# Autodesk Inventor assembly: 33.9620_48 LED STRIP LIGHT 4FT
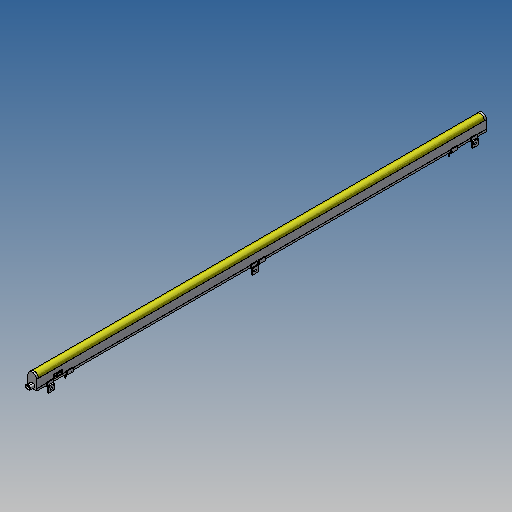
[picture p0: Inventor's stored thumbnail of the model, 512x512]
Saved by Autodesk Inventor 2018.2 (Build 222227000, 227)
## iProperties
Created: 2018-05
Part Number: 33.9620_48 LED STRIP LIGHT 4FT
Document SubType Name: Assembly
Designer: amoles
Author: amoles
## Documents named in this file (6)
- Y:\INVENTOR LIBRARIES\PARTS LIBRARY\WORKSTATION\LIGHTS OUTWATER PLASTICS\33.9620_48 LED STRIP LIGHT 4FT.iam
- Y:\INVENTOR LIBRARIES\PARTS LIBRARY\WORKSTATION\LIGHTS OUTWATER PLASTICS\SUBCOMPONENTS\33.9620 PLASTIC MOUNTING CLIP IN LINE.ipt
- Y:\INVENTOR LIBRARIES\PARTS LIBRARY\WORKSTATION\LIGHTS OUTWATER PLASTICS\SUBCOMPONENTS\33.9620 PLASTIC MOUNTING CLIP OFFSET.ipt
- Y:\INVENTOR LIBRARIES\PARTS LIBRARY\WORKSTATION\LIGHTS OUTWATER PLASTICS\SUBCOMPONENTS\33.9620_48 LED STRIP LIGHT 4FT.ipt
- Y:\INVENTOR LIBRARIES\PARTS LIBRARY\WORKSTATION\LIGHTS OUTWATER PLASTICS\SUBCOMPONENTS\33.9620 RECEPTACLE COVER.ipt
- Y:\INVENTOR LIBRARIES\PARTS LIBRARY\WORKSTATION\LIGHTS OUTWATER PLASTICS\SUBCOMPONENTS\33.9620 M3.9 MOUNTING SCREW.ipt
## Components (11 placed, 5 different names)
1. 33.9620_48 LED STRIP LIGHT 4FT:1 — Mate:1, Flush:1, Flush:4, Flush:6, Flush:10, Flush:11, Mate:2, Flush:12, Flush:13, Mate:3, Angle:1, Mate:4, Mate:5, Mate:7, Mate:8
2. 33.9620 PLASTIC MOUNTING CLIP IN LINE:1 — Mate:1, Flush:1, Flush:2, Flush:3, Flush:4, Flush:5, Flush:7, Insert:2
3. 33.9620 PLASTIC MOUNTING CLIP IN LINE:2 — Flush:2, Flush:3, Flush:8, Flush:9, Flush:12, Insert:1
4. 33.9620 PLASTIC MOUNTING CLIP OFFSET:1 — Flush:5, Flush:6, Flush:7
5. 33.9620 PLASTIC MOUNTING CLIP OFFSET:2 — Flush:8, Flush:9, Flush:10
6. 33.9620 RECEPTACLE COVER:1 — Mate:3, Angle:1, Mate:4
7. 33.9620 M3.9 MOUNTING SCREW:1 — Insert:2
8. 33.9620 M3.9 MOUNTING SCREW:2 — Insert:1
9. 33.9620 PLASTIC MOUNTING CLIP IN LINE:3 — Mate:5, Mate:7, Mate:8, Insert:3, Flush:14, Flush:15
10. 33.9620 M3.9 MOUNTING SCREW:3 — Insert:3
11. 33.9620 PLASTIC MOUNTING CLIP OFFSET:3 — Flush:14, Flush:15
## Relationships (26: Flush 15, Mate 7, Insert 3, Angle 1)
- Mate:1: 33.9620_48 LED STRIP LIGHT 4FT:1 ↔ 33.9620 PLASTIC MOUNTING CLIP IN LINE:1
- Flush:1: 33.9620_48 LED STRIP LIGHT 4FT:1 ↔ 33.9620 PLASTIC MOUNTING CLIP IN LINE:1
- Flush:2: 33.9620 PLASTIC MOUNTING CLIP IN LINE:1 ↔ 33.9620 PLASTIC MOUNTING CLIP IN LINE:2
- Flush:3: 33.9620 PLASTIC MOUNTING CLIP IN LINE:1 ↔ 33.9620 PLASTIC MOUNTING CLIP IN LINE:2
- Flush:4: 33.9620_48 LED STRIP LIGHT 4FT:1 ↔ 33.9620 PLASTIC MOUNTING CLIP IN LINE:1
- Flush:5: 33.9620 PLASTIC MOUNTING CLIP IN LINE:1 ↔ 33.9620 PLASTIC MOUNTING CLIP OFFSET:1
- Flush:6: 33.9620_48 LED STRIP LIGHT 4FT:1 ↔ 33.9620 PLASTIC MOUNTING CLIP OFFSET:1
- Flush:7: 33.9620 PLASTIC MOUNTING CLIP IN LINE:1 ↔ 33.9620 PLASTIC MOUNTING CLIP OFFSET:1
- Flush:8: 33.9620 PLASTIC MOUNTING CLIP IN LINE:2 ↔ 33.9620 PLASTIC MOUNTING CLIP OFFSET:2
- Flush:9: 33.9620 PLASTIC MOUNTING CLIP IN LINE:2 ↔ 33.9620 PLASTIC MOUNTING CLIP OFFSET:2
- Flush:10: 33.9620_48 LED STRIP LIGHT 4FT:1 ↔ 33.9620 PLASTIC MOUNTING CLIP OFFSET:2
- Flush:11: 33.9620_48 LED STRIP LIGHT 4FT:1
- Mate:2: 33.9620_48 LED STRIP LIGHT 4FT:1
- Flush:12: 33.9620_48 LED STRIP LIGHT 4FT:1 ↔ 33.9620 PLASTIC MOUNTING CLIP IN LINE:2
- Flush:13: 33.9620_48 LED STRIP LIGHT 4FT:1
- Mate:3: 33.9620_48 LED STRIP LIGHT 4FT:1 ↔ 33.9620 RECEPTACLE COVER:1
- Angle:1: 33.9620_48 LED STRIP LIGHT 4FT:1 ↔ 33.9620 RECEPTACLE COVER:1
- Mate:4: 33.9620_48 LED STRIP LIGHT 4FT:1 ↔ 33.9620 RECEPTACLE COVER:1
- Insert:1: 33.9620 PLASTIC MOUNTING CLIP IN LINE:2 ↔ 33.9620 M3.9 MOUNTING SCREW:2
- Insert:2: 33.9620 PLASTIC MOUNTING CLIP IN LINE:1 ↔ 33.9620 M3.9 MOUNTING SCREW:1
- Mate:5: 33.9620_48 LED STRIP LIGHT 4FT:1 ↔ 33.9620 PLASTIC MOUNTING CLIP IN LINE:3
- Mate:7: 33.9620_48 LED STRIP LIGHT 4FT:1 ↔ 33.9620 PLASTIC MOUNTING CLIP IN LINE:3
- Mate:8: 33.9620_48 LED STRIP LIGHT 4FT:1 ↔ 33.9620 PLASTIC MOUNTING CLIP IN LINE:3
- Insert:3: 33.9620 PLASTIC MOUNTING CLIP IN LINE:3 ↔ 33.9620 M3.9 MOUNTING SCREW:3
- Flush:14: 33.9620 PLASTIC MOUNTING CLIP IN LINE:3 ↔ 33.9620 PLASTIC MOUNTING CLIP OFFSET:3
- Flush:15: 33.9620 PLASTIC MOUNTING CLIP IN LINE:3 ↔ 33.9620 PLASTIC MOUNTING CLIP OFFSET:3
